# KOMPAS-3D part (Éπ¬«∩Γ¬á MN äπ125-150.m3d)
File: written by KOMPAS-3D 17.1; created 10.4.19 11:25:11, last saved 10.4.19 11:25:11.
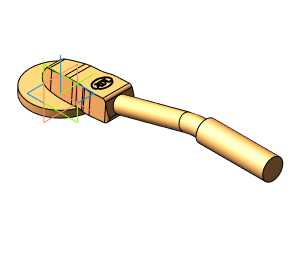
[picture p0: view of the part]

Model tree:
1. Операция без истории:1  (labels: Сталь 20  ГОСТ 1050-2013)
